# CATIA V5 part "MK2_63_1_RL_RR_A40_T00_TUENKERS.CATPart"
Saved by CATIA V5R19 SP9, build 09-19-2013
Part number: MK2_63_1_RL_RR_A40_T00_TUENKERS
Material "MISCHDICHTE": density 4989.5 kg/m3, Young's modulus 2e+11 Pa, Poisson ratio 0.266
Bounding box of the stored display mesh (mm): x -193.5 to 144, y -100.5 to 73, z -122.161 to 122.161
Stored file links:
  G:\Konstruktion\Modelle\Catia_V5\MK2_63_1_RL_RR_A40_T00_TUENKERS.CATPart
  G:\Konstruktion\Modelle\Catia_V5\MK2_63_1_A40_T12_TUENKERS.CATPart
  C:\Catia\Tuenkers_B19SP9HF86_64\win_b64\reffiles\standard\MetricThickPitch.txt
  G:\Konstruktion\Modelle\Catia_V5\MK2_63_1_A10_T12_TUENKERS.CATPart
  G:\Konstruktion\Modelle\Catia_V5\V2_63_1_BR3_ZL_ZR_RL_RR_A40_T12_TUENKERS.CATPart
  HANDHEBEL_KPL_50_63_TUENKERS.CATPart
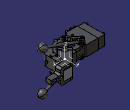
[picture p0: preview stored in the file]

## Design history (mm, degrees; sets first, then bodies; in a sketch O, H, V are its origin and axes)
AxisSystem1: origin (0, 0, 0), X (1, 0, 0), Y (0, 1, 0), Z (0, 0, 1)
Body1 (main body)
  Body2 "*DIT1\\*DIT3"
    Solid1 "Solid.1": solid without history
  Assemble1: tool Body2
  Body3 "*DIT1\\*DIT12\\*DIT16\\"
    Solid2 "Solid.1": solid without history
  Assemble2: tool Body3
  Body4 "*DIT1\\*DIT12\\*DIT17\\"
    Solid3 "Solid.1": solid without history
  Assemble3: tool Body4
  Body5 "*DIT1\\*DIT12\\MK_MK2_63_1_A10_A11_A12_T12_081112_3D_xSET4_2.1"
    Solid4 "Solid.1": solid without history
    Body6 "*DIT1\\*DIT12\\MK_MK2_63_1_A10_A11_A12_T12_081112_3D_xSET4_2.1\\Body.11 ( *SOL16 - wsp GEHAEUSE -  )"
      Solid5 "Solid.1": solid without history
    Add1 "*DIT1\\*DIT12\\MK_MK2_63_1_A10_A11_A12_T12_081112_3D_xSET4_2.1\\Body.11 ( *SOL16 - wsp GEHAEUSE -  )": tool Body6
    Body7 "*DIT1\\*DIT12\\MK_MK2_63_1_A10_A11_A12_T12_081112_3D_xSET4_2.1\\Body.12 ( *SOL17 - wsp GEHAEUSE -  )"
      Solid6 "Solid.1": solid without history
    Add2 "*DIT1\\*DIT12\\MK_MK2_63_1_A10_A11_A12_T12_081112_3D_xSET4_2.1\\Body.12 ( *SOL17 - wsp GEHAEUSE -  )": tool Body7
    Body8 "*DIT1\\*DIT12\\MK_MK2_63_1_A10_A11_A12_T12_081112_3D_xSET4_2.1\\Body.14 ( *SOL18 - wsp GEHAEUSE -  )"
      Solid7 "Solid.1": solid without history
    Add3 "*DIT1\\*DIT12\\MK_MK2_63_1_A10_A11_A12_T12_081112_3D_xSET4_2.1\\Body.14 ( *SOL18 - wsp GEHAEUSE -  )": tool Body8
  Assemble4: tool Body5
  Body9 "*DIT1\\MK_MK2_63_1_A10_A11_A12_T12_081112_3D_xSET2_1.1"
    Solid8 "Solid.1": solid without history
    Sketch1 on face of Solid8, origin (0, 0, 91.5), H (1, 0, 0), V (0, 1, 0)
      line L1 (-107.5, 25) -> (-93.5, 25)
      line L2 (-93.5, 25) -> (-93.5, -25)
      line L3 (-93.5, -25) -> (-107.5, -25)
      line L4 (-107.5, -25) -> (-107.5, 25)
      reference projected line E1 (-93.5, 25) -> (-93.5, -25) from edge [face of Solid8 | face of Solid8]
      reference projected line E2 (-150.5, 25) -> (-93.5, 25) from edge [face of Solid8 | face of Solid8]
      reference projected line E3 (-150.5, -25) -> (-93.5, -25) from edge [face of Solid8 | face of Solid8]
      line L5 (-137.2, 25) -> (-125.7, 25)
      line L6 (-125.7, 25) -> (-125.7, -5)
      line L7 (-125.7, -5) -> (-137.2, -5)
      line L8 (-137.2, -5) -> (-137.2, 25)
      reference projected line E4 (-150.5, 25) -> (-93.5, 25) from edge [face of Solid8 | face of Solid8]
      distance L2 E1 = 0
      distance L1 E2 = 0
      distance E3 L3 = 0
      distance L4 L2 = 14
      distance L6 L4 = 18.2
      distance L5 E4 = 0
      distance L8 L6 = 11.5
      distance L7 L5 = 30
      horizontal: L1 H, L3 H, L5 H, L7 H
      vertical: L2 V, L4 V, L6 V, L8 V
    Pad1: profile Sketch1, direction (0, 0, 1), length 9
    Chamfer1: length 9, angle 45, on edge [face of Pad1 from Sketch1.L8 | end face of Pad1]
    Chamfer2: length 10.5, angle 45, on edge [face of Pad1 | end face of Pad1]
  Assemble5: tool Body9
  Rotate1: Axis edge [XY plane of AxisSystem1 | ZX plane of AxisSystem1], Angle 90, ToTransfor Assemble5
  Body10
    Body11 "*DIT1\\MK_MK2_63_1_A10_A11_A12_T12_081112_3D_xSET2_1.1\\Body.2 ( *SOL2 - wsp MK_MK2 63_1 -  )"
      Solid9 "Solid.1": solid without history
    Assemble6: tool Body11
    Body12 "*DIT1\\MK_MK2_63_1_A10_A11_A12_T12_081112_3D_xSET2_1.1\\Body.3 ( *SOL3 - wsp MK_MK2 63_1 -  )"
      Solid10 "Solid.1": solid without history
    Assemble7: tool Body12
    Body13 "*DIT1\\MK_MK2_63_1_A10_A11_A12_T12_081112_3D_xSET2_1.1\\Body.4 ( *SOL4 - wsp MK_MK2 63_1 -  )"
      Solid11 "Solid.1": solid without history
    Assemble8: tool Body13
    Body14 "*DIT1\\MK_MK2_63_1_A10_A11_A12_T12_081112_3D_xSET2_1.1\\Body.5 ( *SOL5 - wsp MK_MK2 63_1 -  )"
      Solid12 "Solid.1": solid without history
    Assemble9: tool Body14
    Body15 "*DIT1\\MK_MK2_63_1_A10_A11_A12_T12_081112_3D_xSET2_1.1\\Body.6 ( *SOL6 - wsp MK_MK2 63_1 -  )"
      Solid13 "Solid.1": solid without history
    Assemble10: tool Body15
    Rotate2: Axis edge, Angle 90, ToTransfor Assemble10
    Translate1: Direction edge [YZ plane of AxisSystem1 | XY plane of AxisSystem1], Length -1, ToTransfor Rotate2
  Assemble11: tool Body10
Body16 "Spannarm_kpl_63_A40_242839_Tuenkers", material "Steel"
  Sketch2 on xy-plane, origin (0, 0, 0), H (1, 0, 0), V (0, 1, 0)
    line L1 (73, 144) -> (45, 144)
    arc A1 centre (53, 43.1005) radius 20 from (67.1421, 28.9584) to (73, 43.1005) ccw
    line L2 (67.1421, 28.9584) -> (19.0919, -19.0919)
    line L3 (10.9602, 10.9602) -> (10.9602, -10.9602)
    line L4 (10.9602, 10.9602) -> (-10.9602, 10.9602)
    line L5 (-19.0919, 19.0919) -> (-10.9602, 10.9602)
    line L6 (-1.4396, 36.7442) -> (-19.0919, 19.0919)
    line L7 (38.4202, 51.252) -> (-1.4396, 36.7442)
    arc A2 centre (35, 60.6489) radius 10 from (38.4202, 51.252) to (45, 60.6489) ccw
    line L8 (45, 60.6489) -> (45, 144)
    line L9 (73, 144) -> (73, 43.1005)
    line L10 (10.9602, -10.9602) -> (19.0919, -19.0919)
    point P7 (10.9602, 10.9602)
    point P10 (-1.4396, 36.7442)
    point P13 (73, 37.6447)
    point P14 (45, 51.7188)
    reference intersected line E1 through (0, 0) direction (-0.7071, 0.7071)
    reference intersected line E2 through (0, 0) direction (-0.7071, 0.7071)
    reference intersected line E3 through (0, 0) direction (-0.7071, 0.7071)
    reference intersected line E4 through (0, 0) direction (0, 1) from yz-plane
    reference intersected line E5 through (0, 0) direction (-1, 0) from zx-plane
    reference intersected line E6 through (0, 0) direction (0, 1) from yz-plane
    angle L6 L7 = 25
    radius A1 = 20
    angle L4 L5 = 45
    distance P7 L2 = 27
    distance L2 L6 = 54
    angle L2 L10 = 90
    distance P7 E1 = 15.5
    distance E4 L3 = 10.9602
    distance E5 L1 = 144
    distance E6 L8 = 45
    distance L9 L8 = 28
    radius A2 = 10
    distance P10 L1 = 107.2558
    tangency: A1 L2, L8 A2, A2 L7, L9 A1
    coincidence: L10 E2, L5 E3
  Pad2: profile Sketch2, direction (0, 0, 1), length 39, opposite side length 39
  Chamfer3: length 0.1, angle 45, on edge [face of Pad2 from Sketch2.L3 | end face of Pad2]; edge [face of Pad2 from Sketch2.L4 | end face of Pad2]; edge [start face of Pad2 | face of Pad2 from Sketch2.L4]; edge [start face of Pad2 | face of Pad2 from Sketch2.L3]
  Sketch3 on face of Pad2 from Sketch2.L9, origin (73, 0, 0), H (0, 1, 0), V (0, 0, 1)
    line L1 (144, -10) -> (144, 10)
    line L2 (103, 10) -> (144, 10)
    arc A1 centre (103, 18) radius 8 from (103, 10) to (95, 18) cw
    line L3 (95, 18) -> (95, 29)
    arc A2 centre (85, 29) radius 10 from (85, 39) to (95, 29) cw
    line L4 (-20, 39) -> (85, 39)
    line L5 (-20, 39) -> (-20, 27)
    line L6 (74, 27) -> (-20, 27)
    arc A3 centre (74, 21) radius 6 from (74, 27) to (80, 21) cw
    line L7 (80, 21) -> (80, -21)
    arc A4 centre (74, -21) radius 6 from (80, -21) to (74, -27) cw
    line L8 (-20, -27) -> (74, -27)
    line L9 (-20, -27) -> (-20, -39)
    line L10 (-20, -39) -> (85, -39)
    arc A5 centre (85, -29) radius 10 from (95, -29) to (85, -39) cw
    line L11 (95, -29) -> (95, -18)
    arc A6 centre (103, -18) radius 8 from (95, -18) to (103, -10) cw
    line L12 (103, -10) -> (144, -10)
    reference intersected line E1 through (0, 0) direction (-1, 0) from xy-plane
    reference intersected line E2 through (0, 0) direction (0, 1) from zx-plane
    reference intersected line E3 through (0, 0) direction (0, 1) from zx-plane
    reference intersected line E4 through (0, 0) direction (0, 1) from zx-plane
    line L13 (-30, -44) -> (160, -44)
    line L14 (160, -44) -> (160, 44)
    line L15 (160, 44) -> (-30, 44)
    line L16 (-30, 44) -> (-30, -44)
    reference intersected line E5 through (0, 0) direction (-1, 0) from xy-plane
    reference intersected line E6 through (0, 0) direction (0, 1) from zx-plane
    distance L12 E1 = 10
    distance L12 L2 = 20
    distance L4 L10 = 78
    distance L6 L8 = 54
    distance L10 L12 = 29
    distance L8 L10 = 12
    radius A3 = 6
    radius A4 = 6
    radius A5 = 10
    radius A2 = 10
    radius A1 = 8
    radius A6 = 8
    distance L7 E2 = 80
    distance L3 E3 = 95
    distance L1 L5 = 164
    distance E4 L1 = 144
    distance L16 L14 = 190
    distance L15 L13 = 88
    distance L13 E5 = 44
    distance L14 E6 = 160
    tangency: L6 A3, A3 L7, L7 A4, A4 L8, L10 A5, A5 L11, L3 A1, A1 L2, A6 L12, A2 L4, A2 L3, A6 L11
    vertical: L1 V, L14 V, L16 V
    horizontal: L12 H, L13 H, L15 H
    coincidence: L5 L9, L11 L3
  Pocket1: profile Sketch3, direction (-1, 0, 0), length 95
  Sketch4 on face of Pad2 from Sketch2.L9, origin (73, 131.0889, -0.3784), H (0, 1, 0), V (0, 0, 1)
    point P1 (3.9111, 0.3784)
    reference intersected line E1 through (0, 0.3784) direction (-1, 0) from xy-plane
    reference intersected line E2 through (-131.0889, 0) direction (0, 1) from zx-plane
    reference intersected line E3 through (-131.0889, 0) direction (0, 1) from zx-plane
    reference intersected line E4 (12.9111, -38.6216) -> (-87.9884, -38.6216) from start face of Pad2
    distance P1 E2 = 135
    distance E3 E4 = 0
    coincidence: P1 E1
  Hole1: placed by Sketch4, at (73, 135, 0) direction (-1, 0, 0), diameter 6, through (limit type 6)
  Sketch5 on face of Pad2 from Sketch2.L9, origin (73, 113.9529, 0.5693), H (0, 1, 0), V (0, 0, 1)
    point P1 (-8.9529, -0.5693)
    reference projected point E1 (21.0471, -0.5693) from axis of face of Hole1
    reference intersected line E2 through (0, -0.5693) direction (-1, 0) from xy-plane
    distance P1 E1 = 30
    coincidence: P1 E2
  Hole2: placed by Sketch5, at (73, 105, 0) direction (-1, 0, 0), diameter 6, through (limit type 6)
  Sketch6 on face of Pad2 from Sketch2.L9, origin (73, 123.4122, -0.1089), H (0, 1, 0), V (0, 0, 1)
    point P1 (-3.4122, 0.1089)
    reference projected point E1 (11.5878, 0.1089) from axis of face of Hole1
    reference projected point E2 (-18.4122, 0.1089) from axis of face of Hole2
    distance P1 E1 = 15
    distance E2 P1 = 15
  Hole3: placed by Sketch6, at (73, 120, 0) direction (-1, 0, 0), diameter 9, through (limit type 6)
  Sketch7 on face of Pad2 from Sketch2.L9, origin (73, 93.5248, 1.4062), H (0, 1, 0), V (0, 0, 1)
    point P1 (-3.5248, -1.4062)
    reference projected point E1 (26.4752, -1.4062) from axis of face of Hole3
    reference projected point E2 (11.4752, -1.4062) from axis of face of Hole2
    distance P1 E1 = 30
    distance P1 E2 = 15
  Hole4: placed by Sketch7, at (73, 90, 0) direction (-1, 0, 0), diameter 9, through (limit type 6)
  Sketch8 on face of Pad2 from Sketch2.L10, origin (13.7879, -13.7879, 28.7565), H (0.7071, -0.7071, 0), V (0, 0, 1)
    point P1 (0.5009, 4.2435)
    reference intersected line E1 through (0, -28.7565) direction (-1, 0) from xy-plane
    reference projected line E2 (-19.4991, -67.7565) -> (-19.4991, 10.2435) from edge [face of Pad2 from Sketch2.L3 | face of Pad2 from Sketch2.L4]
    distance P1 E1 = 33
    distance E2 P1 = 20
  Hole5: placed by Sketch8, at (14.1421, -14.1421, 33) direction (0.7071, 0.7071, 0), diameter 6.647, depth 18, V-bottom angle 120, threaded "M8", thread diameter 8, thread depth 15, pitch 1.25
  RectPattern1: of Hole5, direction 1 instances 2, spacing 66, along edge [face of Pad2 from Sketch2.L3 | face of Pad2 from Sketch2.L4] reversed, direction 2 instances 2, spacing 40, along edge [face of Pad2 from Sketch2.L10 | face of Pocket1] reversed
  Body17 "KLEMMFLANSCH KPL"
    Sketch9 on xy-plane, origin (0, 0, 0), H (1, 0, 0), V (0, 1, 0)
      line L1 (-20.5061, 17.6777) -> (-31.1375, 7.0463)
      line L2 (-31.1375, 7.0463) -> (-19.1167, -4.9745)
      line L3 (-19.1167, -4.9745) -> (-25.4806, -11.3385)
      line L4 (-25.4806, -11.3385) -> (-11.3385, -25.4806)
      line L5 (-11.3385, -25.4806) -> (-4.9745, -19.1167)
      line L6 (-4.9745, -19.1167) -> (7.0463, -31.1375)
      line L7 (7.0463, -31.1375) -> (19.0671, -19.1167)
      line L8 (19.0671, -19.1167) -> (10.9106, -10.9602)
      line L9 (10.9106, -10.9602) -> (-10.9602, -10.9602)
      point P10 (-10.9602, -10.9602)
      line L10 (-10.9602, -10.9602) -> (-10.9602, 8.1317)
      line L11 (-10.9602, 8.1317) -> (-20.5061, 17.6777)
      reference intersected line E1 through (0, 0) direction (-0.7071, 0.7071)
      reference intersected line E2 through (0, 0) direction (-0.7071, 0.7071)
      reference intersected line E3 through (0, 0) direction (-0.7071, -0.7071)
      distance L4 L8 = 26
      distance L7 L5 = 17
      distance L5 L3 = 20
      distance L7 L1 = 54
      distance L4 L6 = 9
      distance E1 P10 = 15.5
      distance L11 E2 = 2
      distance L11 L8 = 1.965
      angle L11 L10 = 135
      angle L9 L8 = 45
      distance L7 P10 = 27
      distance E3 L7 = 27
      coincidence: L2 L6
    Pad3: profile Sketch9, direction (0, 0, 1), length 39, opposite side length -27
    Chamfer4: length 0.1, angle 45, on edge [face of Pad3 from Sketch9.L9 | end face of Pad3]; edge [face of Pad3 from Sketch9.L10 | end face of Pad3]
    Sketch10 on face of Pad3 from Sketch9.L6, origin (-12.0456, -12.0456, 0), H (0.7071, -0.7071, 0), V (0, 0, 1)
      circle A1 centre (20, 33) radius 4
      point P1 (20, 33)
      circle A2 centre (-20, 33) radius 4
      point P2 (-20, 33)
      reference projected line E1 (-27, 27) -> (-10, 27) from edge [start face of Pad3 | face of Pad3 from Sketch9.L2]
      reference projected line E2 (10, 27) -> (27, 27) from edge [start face of Pad3 | face of Pad3 from Sketch9.L6]
      reference projected line E3 (27, 27) -> (27, 39) from edge [face of Pad3 from Sketch9.L7 | face of Pad3 from Sketch9.L6]
      reference projected line E4 (-27, 27) -> (-27, 39) from edge [face of Pad3 from Sketch9.L2 | face of Pad3 from Sketch9.L1]
      radius A1 = 4
      radius A2 = 4
      distance E1 P2 = 6
      distance P1 E2 = 6
      distance E3 P1 = 7
      distance P2 E4 = 7
    Pad4: profile Sketch10, direction (0.7071, 0.7071, 0), length 20
    Sketch11 on face of Pad4, origin (-12.0456, -12.0456, 0), H (0.7071, -0.7071, 0), V (0, 0, 1)
      circle A1 centre (20, 33) radius 6.5
      point P1 (20, 33)
      circle A2 centre (-20, 33) radius 6.5
      point P2 (-20, 33)
      reference projected line E1 (-27, 27) -> (-27, 39) from edge [face of Pad3 from Sketch9.L2 | face of Pad3 from Sketch9.L1]
      reference projected line E2 (27, 27) -> (27, 39) from edge [face of Pad3 from Sketch9.L7 | face of Pad3 from Sketch9.L6]
      reference projected line E3 (-27, 27) -> (-10, 27) from edge [start face of Pad3 | face of Pad3 from Sketch9.L2]
      reference projected line E4 (10, 27) -> (27, 27) from edge [start face of Pad3 | face of Pad3 from Sketch9.L6]
      radius A1 = 6.5
      radius A2 = 6.5
      distance E1 P2 = 7
      distance E2 P1 = 7
      distance E3 P2 = 6
      distance E4 P1 = 6
    Pad5: profile Sketch11, direction (-0.7071, -0.7071, 0), length 1.4
    Chamfer5: length 0.1, angle 45, on edge [face of Pad5 from Sketch11.A1 | end face of Pad5]; edge [face of Pad5 from Sketch11.A2 | end face of Pad5]
    Sketch12 on end face of Pad5, origin (-13.0355, -13.0355, 0), H (0.7071, -0.7071, 0), V (0, 0, 1)
      circle A1 centre (20, 33) radius 6.5
      point P1 (20, 33)
      circle A2 centre (-20, 33) radius 6.5
      point P2 (-20, 33)
      reference projected line E1 (10, 27) -> (27, 27) from edge [start face of Pad3 | face of Pad4]
      reference projected line E2 (27, 27) -> (27, 39) from edge [face of Pad3 from Sketch9.L7 | face of Pad3 from Sketch9.L6]
      reference projected line E3 (-27, 27) -> (-27, 39) from edge [face of Pad3 from Sketch9.L2 | face of Pad3 from Sketch9.L1]
      reference projected line E4 (-27, 27) -> (-10, 27) from edge [start face of Pad3 | face of Pad4]
      radius A1 = 6.5
      radius A2 = 6.5
      distance E1 P1 = 6
      distance E2 P1 = 7
      distance E3 P2 = 7
      distance E4 P2 = 6
    Pad6: profile Sketch12, direction (-0.7071, -0.7071, 0), length 8
    Fillet1: radius 0.5, on end face of Pad6; edge [face of Pad6 from Sketch12.A1 | end face of Pad6]
    Mirror1: of the body so far, about xy-plane, deactivated
    Translate2: Direction edge [ZX plane of AxisSystem1 | YZ plane of AxisSystem1], Length -66, ToTransfor Mirror1
  Assemble12: tool Body17
  Rotate3: Axis edge [XY plane of AxisSystem1 | ZX plane of AxisSystem1], Angle 180, ToTransfor Assemble12
  Rotate4: Axis edge [ZX plane of AxisSystem1 | YZ plane of AxisSystem1], Angle 90, ToTransfor Rotate3
Body18 "ENDLAGENRASTE_RECHTS"
  Body19 "LUMP69"
    Solid14 "Manifold Solid #2521": solid without history
  Assemble13: tool Body19
  Body20 "LUMP71"
    Solid15 "Manifold Solid #3035": solid without history
  Assemble14: tool Body20
  Body21 "LUMP72"
    Solid16 "Manifold Solid #3745": solid without history
  Assemble15: tool Body21
  Body22 "LUMP75"
    Solid17 "Manifold Solid #6741": solid without history
  Assemble16: tool Body22
  Body23 "LUMP77"
    Solid18 "Manifold Solid #7511": solid without history
  Assemble17: tool Body23
  Body24 "LUMP78"
    Solid19 "Manifold Solid #7920": solid without history
  Assemble18: tool Body24
  Body25 "LUMP80"
    Solid20 "Manifold Solid #8586": solid without history
  Assemble19: tool Body25
  Body26 "LUMP83"
    Solid21 "Manifold Solid #9661": solid without history
  Assemble20: tool Body26
  Body27 "LUMP84"
    Solid22 "Manifold Solid #9918": solid without history
  Assemble21: tool Body27
  Body28 "LUMP86"
    Solid23 "Manifold Solid #10584": solid without history
  Assemble22: tool Body28
  Body29 "LUMP90"
    Solid24 "Manifold Solid #12531": solid without history
  Assemble23: tool Body29
  Body30 "LUMP91"
    Solid25 "Manifold Solid #13299": solid without history
  Assemble24: tool Body30
  Body31 "LUMP92"
    Solid26 "Manifold Solid #13708": solid without history
  Assemble25: tool Body31
  Body32 "LUMP95"
    Solid27 "Manifold Solid #14479": solid without history
    Translate3: Direction edge [face of Solid25 | face of Solid25], Length -4, ToTransfor Solid27
  Assemble26: tool Body32
  Body33 "LUMP96"
    Solid28 "Manifold Solid #14736": solid without history
    Translate4: Direction edge [face of Solid25 | face of Solid25], Length -4, ToTransfor Solid28
  Assemble27: tool Body33
  Body34 "LUMP99"
    Solid29 "Manifold Solid #15963": solid without history
    Translate5: Direction edge [face of Solid25 | face of Solid25], Length -4, ToTransfor Solid29
  Assemble28: tool Body34
  Body35 "LUMP100"
    Solid30 "Manifold Solid #16372": solid without history
    Translate6: Direction edge [face of Solid25 | face of Solid25], Length -4, ToTransfor Solid30
  Assemble29: tool Body35
  Body36 "LUMP103"
    Solid31 "Manifold Solid #17295": solid without history
  Assemble30: tool Body36
  Rotate5: Axis edge, Angle 90, ToTransfor Assemble30
Body37 "ENDLAGENRASTE_LINKS"
  Solid32 "Manifold Solid #1213": solid without history
  Body38 "LUMP70"
    Solid33 "Manifold Solid #2778": solid without history
  Assemble31: tool Body38
  Body39 "LUMP73"
    Solid34 "Manifold Solid #4455": solid without history
  Assemble32: tool Body39
  Body40 "LUMP74"
    Solid35 "Manifold Solid #5598": solid without history
  Assemble33: tool Body40
  Body41 "LUMP76"
    Solid36 "Manifold Solid #7126": solid without history
  Assemble34: tool Body41
  Body42 "LUMP79"
    Solid37 "Manifold Solid #8329": solid without history
  Assemble35: tool Body42
  Body43 "LUMP81"
    Solid38 "Manifold Solid #8843": solid without history
  Assemble36: tool Body43
  Body44 "LUMP82"
    Solid39 "Manifold Solid #9252": solid without history
  Assemble37: tool Body44
  Body45 "LUMP85"
    Solid40 "Manifold Solid #10175": solid without history
  Assemble38: tool Body45
  Body46 "LUMP87"
    Solid41 "Manifold Solid #10993": solid without history
  Assemble39: tool Body46
  Body47 "LUMP88"
    Solid42 "Manifold Solid #11378": solid without history
  Assemble40: tool Body47
  Body48 "LUMP89"
    Solid43 "Manifold Solid #12146": solid without history
  Assemble41: tool Body48, deactivated
  Body49 "LUMP93"
    Solid44 "Manifold Solid #13965": solid without history
  Assemble42: tool Body49, deactivated
  Body50 "LUMP94"
    Solid45 "Manifold Solid #14222": solid without history
  Assemble43: tool Body50, deactivated
  Body51 "LUMP97"
    Solid46 "Manifold Solid #15145": solid without history
  Assemble44: tool Body51, deactivated
  Body52 "LUMP98"
    Solid47 "Manifold Solid #15554": solid without history
  Assemble45: tool Body52, deactivated
  Body53 "LUMP101"
    Solid48 "Manifold Solid #16781": solid without history
  Assemble46: tool Body53
  Body54 "LUMP102"
    Solid49 "Manifold Solid #17038": solid without history
  Assemble47: tool Body54
  Rotate6: Axis edge, Angle 90, ToTransfor Assemble47
Body55 "Handhebel_KPL_218625_TUENKERS.1"
  Solid50: solid without history
  Body56 "Handhebel_KPL_218625_TUENKERS.2"
    Solid51: solid without history
  Assemble48: tool Body56
  Translate7: Direction edge [ZX plane of AxisSystem1 | YZ plane of AxisSystem1], ToTransfor Assemble48, Length 28
  Translate8: Direction edge [XY plane of AxisSystem1 | ZX plane of AxisSystem1], ToTransfor Translate7, Length -86
  Translate9: Direction edge [YZ plane of AxisSystem1 | XY plane of AxisSystem1], ToTransfor Translate8, Length -4
Body57 "Handhebel_KPL_218625_TUENKERS.1"
  Solid52: solid without history
  Body58 "Handhebel_KPL_218625_TUENKERS.2"
    Solid53: solid without history
  Assemble49: tool Body58
  Translate10: Direction edge [ZX plane of AxisSystem1 | YZ plane of AxisSystem1], Length 28, ToTransfor Assemble49
  Translate11: Direction edge [XY plane of AxisSystem1 | ZX plane of AxisSystem1], Length -86, ToTransfor Translate10
  Translate12: Direction edge [YZ plane of AxisSystem1 | XY plane of AxisSystem1], Length -4, ToTransfor Translate11
  Symmetry1: ToTransfor Translate12, Reference XY plane of AxisSystem1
